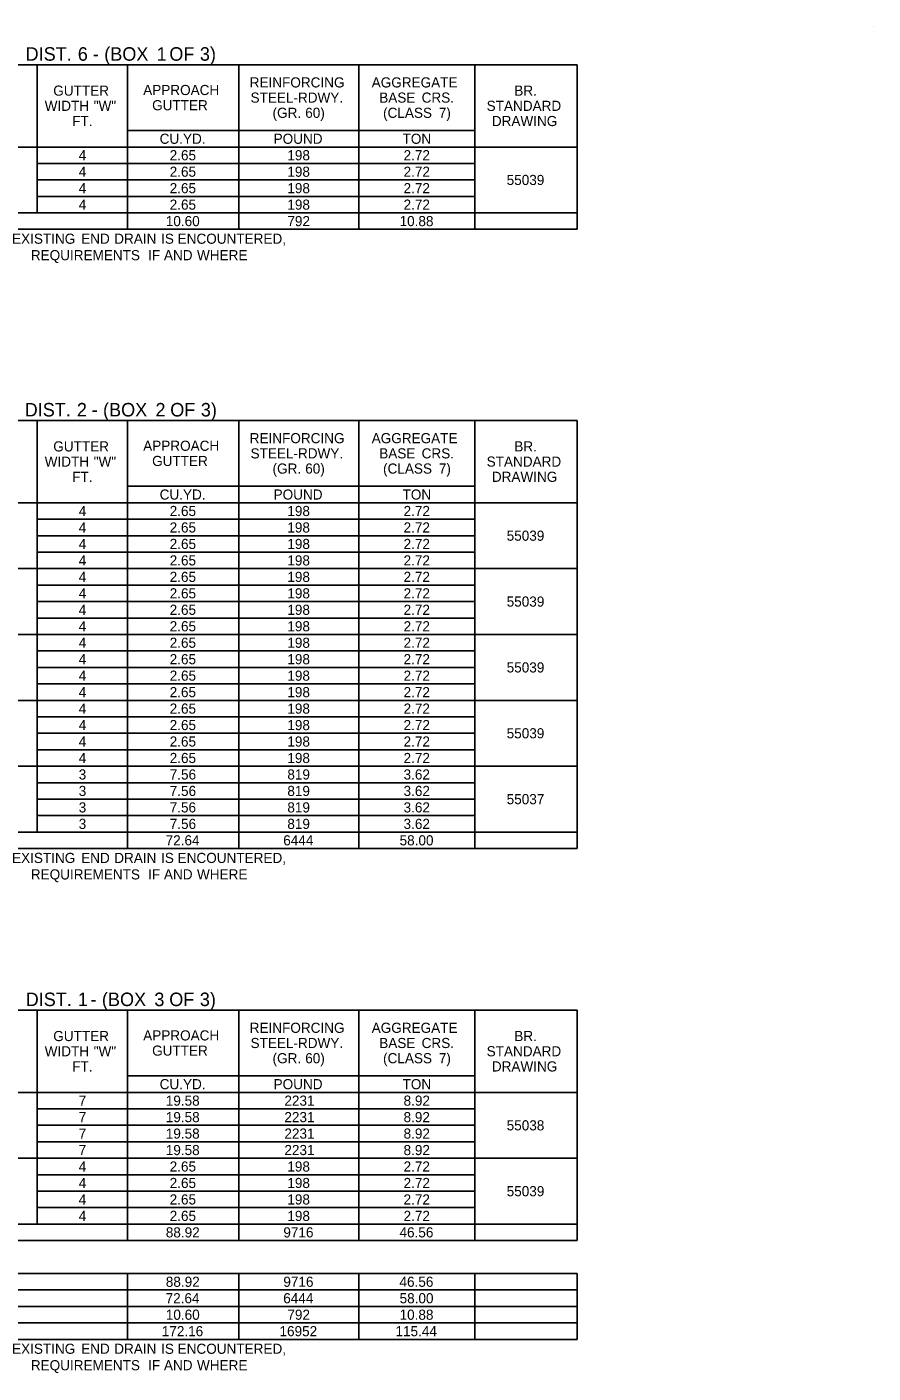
# Model space of a CAD drawing. Extents: x 542596 to 1930787, y -1948294 to 596640.
# Drawn here: x 559810 to 560311, y -1946903 to -1946106 of the extents above; entities that cross this region are included whole.
import ezdxf

# ---------------------------------------------------------------- set-up
doc = ezdxf.new("R2010")
doc.units = 0
doc.layers.add('Default', color=7, linetype='Continuous')

msp = doc.modelspace()

# ---------------------------------------------------------------- linework, layer by layer
at = {"layer": 'Default'}
for p, q in [((560311.42, -1946105.77), (560311.42, -1946105.77)), ((559473.59, -1946128.12), (560136.11, -1946128.12)), ((559816.31, -1946215.87), (559816.31, -1946128.12)), ((559869.93, -1946225.62), (559869.93, -1946128.12)), ((559935.74, -1946225.62), (559935.74, -1946128.12)), ((560006.92, -1946225.62), (560006.92, -1946128.12)), ((560075.66, -1946176.87), (560075.66, -1946128.12)), ((560075.66, -1946225.62), (560075.66, -1946128.12)), ((560136.11, -1946225.62), (560136.11, -1946128.12)), ((559869.93, -1946167.12), (560075.66, -1946167.12)), ((559935.74, -1946176.87), (559935.74, -1946167.12)), ((560006.92, -1946176.87), (560006.92, -1946167.12)), ((559473.59, -1946176.87), (560136.11, -1946176.87)), ((560075.66, -1946176.87), (560136.11, -1946176.87)), ((559816.31, -1946186.62), (560075.66, -1946186.62)), ((559869.93, -1946186.62), (560006.92, -1946186.62)), ((560006.92, -1946186.62), (560075.66, -1946186.62)), ((559816.31, -1946196.37), (560075.66, -1946196.37)), ((559869.93, -1946196.37), (560006.92, -1946196.37)), ((560006.92, -1946196.37), (560075.66, -1946196.37)), ((559816.31, -1946206.12), (560075.66, -1946206.12)), ((559869.93, -1946206.12), (560006.92, -1946206.12)), ((560006.92, -1946206.12), (560075.66, -1946206.12)), ((559473.59, -1946215.87), (560136.11, -1946215.87)), ((559762.68, -1946215.87), (559869.93, -1946215.87)), ((559869.93, -1946215.87), (560006.92, -1946215.87)), ((560006.92, -1946215.87), (560136.11, -1946215.87)), ((560006.92, -1946225.62), (560006.92, -1946215.87)), ((560075.66, -1946225.62), (560075.66, -1946215.87)), ((559473.59, -1946225.62), (560136.11, -1946225.62)), ((559473.59, -1946338.77), (560136.11, -1946338.77)), ((559816.31, -1946582.52), (559816.31, -1946338.77)), ((559869.93, -1946592.27), (559869.93, -1946338.77)), ((559935.74, -1946592.27), (559935.74, -1946338.77)), ((560006.92, -1946592.27), (560006.92, -1946338.77)), ((560075.66, -1946387.52), (560075.66, -1946338.77)), ((560075.66, -1946592.27), (560075.66, -1946338.77)), ((560136.11, -1946592.27), (560136.11, -1946338.77)), ((559869.93, -1946377.77), (560075.66, -1946377.77)), ((559935.74, -1946387.52), (559935.74, -1946377.77)), ((560006.92, -1946387.52), (560006.92, -1946377.77)), ((559473.59, -1946387.52), (560075.66, -1946387.52)), ((560075.66, -1946387.52), (560136.11, -1946387.52)), ((560075.66, -1946387.52), (560136.11, -1946387.52)), ((559816.31, -1946397.27), (560075.66, -1946397.27)), ((559869.93, -1946397.27), (560006.92, -1946397.27)), ((560006.92, -1946397.27), (560075.66, -1946397.27)), ((559816.31, -1946407.02), (560075.66, -1946407.02)), ((559869.93, -1946407.02), (560006.92, -1946407.02)), ((560006.92, -1946407.02), (560075.66, -1946407.02)), ((559816.31, -1946416.77), (560075.66, -1946416.77)), ((559869.93, -1946416.77), (560006.92, -1946416.77)), ((560006.92, -1946416.77), (560075.66, -1946416.77)), ((559473.59, -1946426.52), (560136.11, -1946426.52)), ((559762.68, -1946426.52), (559869.93, -1946426.52)), ((559869.93, -1946426.52), (560006.92, -1946426.52)), ((560006.92, -1946426.52), (560136.11, -1946426.52)), ((559816.31, -1946436.27), (560075.66, -1946436.27)), ((559869.93, -1946436.27), (560006.92, -1946436.27)), ((560006.92, -1946436.27), (560075.66, -1946436.27)), ((559816.31, -1946446.02), (560075.66, -1946446.02)), ((559869.93, -1946446.02), (560006.92, -1946446.02)), ((560006.92, -1946446.02), (560075.66, -1946446.02)), ((559816.31, -1946455.77), (560075.66, -1946455.77)), ((559869.93, -1946455.77), (560006.92, -1946455.77)), ((560006.92, -1946455.77), (560075.66, -1946455.77)), ((559473.59, -1946465.52), (560136.11, -1946465.52)), ((559762.68, -1946465.52), (559869.93, -1946465.52)), ((559869.93, -1946465.52), (560006.92, -1946465.52)), ((560006.92, -1946465.52), (560136.11, -1946465.52)), ((559816.31, -1946475.27), (560075.66, -1946475.27)), ((559869.93, -1946475.27), (560006.92, -1946475.27)), ((560006.92, -1946475.27), (560075.66, -1946475.27)), ((559816.31, -1946485.02), (560075.66, -1946485.02)), ((559869.93, -1946485.02), (560006.92, -1946485.02)), ((560006.92, -1946485.02), (560075.66, -1946485.02)), ((559816.31, -1946494.77), (560075.66, -1946494.77)), ((559869.93, -1946494.77), (560006.92, -1946494.77)), ((560006.92, -1946494.77), (560075.66, -1946494.77)), ((559473.59, -1946504.52), (560136.11, -1946504.52)), ((559762.68, -1946504.52), (559869.93, -1946504.52)), ((559869.93, -1946504.52), (560006.92, -1946504.52)), ((560006.92, -1946504.52), (560136.11, -1946504.52)), ((559816.31, -1946514.27), (560006.92, -1946514.27)), ((559816.31, -1946514.27), (559935.74, -1946514.27)), ((559935.74, -1946514.27), (560075.66, -1946514.27)), ((559816.31, -1946524.02), (560006.92, -1946524.02)), ((559816.31, -1946524.02), (559935.74, -1946524.02)), ((559935.74, -1946524.02), (560075.66, -1946524.02)), ((559816.31, -1946533.77), (560006.92, -1946533.77)), ((559816.31, -1946533.77), (559935.74, -1946533.77)), ((559935.74, -1946533.77), (560075.66, -1946533.77)), ((559473.59, -1946543.52), (560136.11, -1946543.52)), ((559762.68, -1946543.52), (559869.93, -1946543.52)), ((559869.93, -1946543.52), (560006.92, -1946543.52)), ((560006.92, -1946543.52), (560136.11, -1946543.52)), ((559816.31, -1946553.27), (560075.66, -1946553.27)), ((559869.93, -1946553.27), (560006.92, -1946553.27)), ((560006.92, -1946553.27), (560075.66, -1946553.27)), ((559816.31, -1946563.02), (560075.66, -1946563.02)), ((559869.93, -1946563.02), (560006.92, -1946563.02)), ((560006.92, -1946563.02), (560075.66, -1946563.02)), ((559816.31, -1946572.77), (560075.66, -1946572.77)), ((559869.93, -1946572.77), (560006.92, -1946572.77)), ((560006.92, -1946572.77), (560075.66, -1946572.77)), ((559473.59, -1946582.52), (560136.11, -1946582.52)), ((559762.68, -1946582.52), (559869.93, -1946582.52)), ((559869.93, -1946582.52), (560006.92, -1946582.52)), ((560006.92, -1946582.52), (560136.11, -1946582.52)), ((560006.92, -1946592.27), (560006.92, -1946582.52)), ((560075.66, -1946592.27), (560075.66, -1946582.52)), ((559473.59, -1946592.27), (560136.11, -1946592.27)), ((559473.59, -1946687.91), (560136.11, -1946687.91)), ((559816.31, -1946814.66), (559816.31, -1946687.91)), ((559869.93, -1946824.41), (559869.93, -1946687.91)), ((559935.74, -1946824.41), (559935.74, -1946687.91)), ((560006.92, -1946824.41), (560006.92, -1946687.91)), ((560075.66, -1946736.66), (560075.66, -1946687.91)), ((560075.66, -1946824.41), (560075.66, -1946687.91)), ((560136.11, -1946824.41), (560136.11, -1946687.91)), ((559869.93, -1946726.91), (560075.66, -1946726.91)), ((559935.74, -1946736.66), (559935.74, -1946726.91)), ((560006.92, -1946736.66), (560006.92, -1946726.91)), ((559473.59, -1946736.66), (560136.11, -1946736.66)), ((560075.66, -1946736.66), (560136.11, -1946736.66)), ((559816.31, -1946746.41), (560075.66, -1946746.41)), ((559869.93, -1946746.41), (560006.92, -1946746.41)), ((560006.92, -1946746.41), (560075.66, -1946746.41)), ((559816.31, -1946756.16), (560006.92, -1946756.16)), ((559816.31, -1946756.16), (559935.74, -1946756.16)), ((559935.74, -1946756.16), (560075.66, -1946756.16)), ((559816.31, -1946765.91), (560075.66, -1946765.91)), ((559869.93, -1946765.91), (560006.92, -1946765.91)), ((560006.92, -1946765.91), (560075.66, -1946765.91)), ((559473.59, -1946775.66), (560136.11, -1946775.66)), ((559762.68, -1946775.66), (559869.93, -1946775.66)), ((559869.93, -1946775.66), (560006.92, -1946775.66)), ((560006.92, -1946775.66), (560136.11, -1946775.66)), ((559816.31, -1946785.41), (560075.66, -1946785.41)), ((559869.93, -1946785.41), (560006.92, -1946785.41)), ((560006.92, -1946785.41), (560075.66, -1946785.41)), ((559816.31, -1946795.16), (560075.66, -1946795.16)), ((559869.93, -1946795.16), (560006.92, -1946795.16)), ((560006.92, -1946795.16), (560075.66, -1946795.16)), ((559816.31, -1946804.91), (560075.66, -1946804.91)), ((559869.93, -1946804.91), (560006.92, -1946804.91)), ((560006.92, -1946804.91), (560075.66, -1946804.91)), ((559473.59, -1946814.66), (560136.11, -1946814.66)), ((559762.68, -1946814.66), (559869.93, -1946814.66)), ((559869.93, -1946814.66), (560006.92, -1946814.66)), ((560006.92, -1946814.66), (560136.11, -1946814.66)), ((560006.92, -1946824.41), (560006.92, -1946814.66)), ((560075.66, -1946824.41), (560075.66, -1946814.66)), ((559473.59, -1946824.41), (560136.11, -1946824.41)), ((559473.59, -1946843.91), (560136.11, -1946843.91)), ((559473.59, -1946843.91), (560136.11, -1946843.91)), ((559869.93, -1946882.91), (559869.93, -1946843.91)), ((559935.74, -1946882.91), (559935.74, -1946843.91)), ((560006.92, -1946882.91), (560006.92, -1946843.91)), ((560075.66, -1946882.91), (560075.66, -1946843.91)), ((560136.11, -1946882.91), (560136.11, -1946843.91)), ((559473.59, -1946853.66), (560136.11, -1946853.66)), ((559473.59, -1946863.41), (560136.11, -1946863.41)), ((559473.59, -1946873.16), (560136.11, -1946873.16)), ((559869.93, -1946882.91), (559869.93, -1946873.16)), ((559935.74, -1946882.91), (559935.74, -1946873.16)), ((560006.92, -1946882.91), (560006.92, -1946873.16)), ((560075.66, -1946882.91), (560075.66, -1946873.16)), ((559473.59, -1946882.91), (560136.11, -1946882.91))]:
    msp.add_line(p, q, dxfattribs=at)

# ---------------------------------------------------------------- texts
for s, height, p in [(' DIST.', 8, (559806.55, -1946125.78)), (' 6', 8, (559837.46, -1946125.78)), (' (BOX', 8, (559853.12, -1946125.78)), (' 1', 8, (559884.16, -1946125.78)), (' OF', 8, (559891.66, -1946125.78)), (' 3)', 8, (559909.77, -1946125.78)), (' -', 8, (559846.38, -1946125.78)), ('GUTTER', 6, (559825.91, -1946146.49)), ('APPROACH', 6, (559879.17, -1946146.12)), ('REINFORCING', 6, (559942.24, -1946141.62)), ('AGGREGATE', 6, (560014.48, -1946141.62)), ('BR.', 6, (560098.95, -1946146.49)), ('WIDTH', 6, (559820.82, -1946155.49)), (' "W"', 6, (559847.65, -1946155.49)), ('GUTTER', 6, (559884.46, -1946155.12)), ('STEEL-RDWY.', 6, (559942.74, -1946150.62)), ('BASE', 6, (560018.96, -1946150.62)), (' CRS.', 6, (560041.84, -1946150.62)), ('STANDARD', 6, (560082.57, -1946155.49)), ('FT.', 6, (559837.12, -1946164.49)), ('(GR.', 6, (559955.77, -1946159.62)), (' 60)', 6, (559972.89, -1946159.62)), ('(CLASS', 6, (560021.22, -1946159.62)), (' 7)', 6, (560052.01, -1946159.62)), ('DRAWING', 6, (560085.64, -1946164.49)), ('CU.YD.', 6, (559888.92, -1946174.99)), ('POUND', 6, (559956.4, -1946174.99)), ('TON', 6, (560032.77, -1946174.99)), ('4', 6, (559840.99, -1946184.74)), ('2.65', 6, (559894.85, -1946184.74)), ('198', 6, (559964.53, -1946184.74)), ('2.72', 6, (560033.36, -1946184.74)), ('4', 6, (559840.99, -1946194.49)), ('2.65', 6, (559894.85, -1946194.49)), ('198', 6, (559964.53, -1946194.49)), ('2.72', 6, (560033.36, -1946194.49)), ('4', 6, (559840.99, -1946204.24)), ('2.65', 6, (559894.85, -1946204.24)), ('198', 6, (559964.53, -1946204.24)), ('2.72', 6, (560033.36, -1946204.24)), ('55039', 6, (560094.42, -1946199.37)), ('4', 6, (559840.99, -1946213.99)), ('2.65', 6, (559894.85, -1946213.99)), ('198', 6, (559964.53, -1946213.99)), ('2.72', 6, (560033.36, -1946213.99)), ('10.60', 6, (559892.56, -1946223.74)), ('792', 6, (559964.55, -1946223.74)), ('10.88', 6, (560030.99, -1946223.74)), (' EXISTING', 6, (559799.27, -1946234.17)), (' END', 6, (559840.21, -1946234.17)), (' DRAIN', 6, (559859.79, -1946234.17)), (' IS', 6, (559887.52, -1946234.17)), (' ENCOUNTERED,', 6, (559897.33, -1946234.17)), (' REQUIREMENTS', 6, (559810.39, -1946243.92)), (' IF', 6, (559879.83, -1946243.92)), (' AND', 6, (559889.22, -1946243.92)), (' WHERE', 6, (559908.8, -1946243.92)), (' DIST.', 8, (559806.01, -1946336.43)), (' 2', 8, (559836.91, -1946336.43)), (' -', 8, (559845.67, -1946336.43)), (' (BOX', 8, (559852.41, -1946336.43)), (' 2', 8, (559883.45, -1946336.43)), (' OF', 8, (559892.21, -1946336.43)), (' 3)', 8, (559910.32, -1946336.43)), ('REINFORCING', 6, (559942.24, -1946352.27)), ('AGGREGATE', 6, (560014.48, -1946352.27)), ('GUTTER', 6, (559825.91, -1946357.15)), ('APPROACH', 6, (559879.17, -1946356.77)), ('STEEL-RDWY.', 6, (559942.74, -1946361.27)), ('BASE', 6, (560018.96, -1946361.27)), (' CRS.', 6, (560041.84, -1946361.27)), ('BR.', 6, (560098.95, -1946357.15)), ('WIDTH', 6, (559820.82, -1946366.15)), (' "W"', 6, (559847.65, -1946366.15)), ('GUTTER', 6, (559884.46, -1946365.77)), ('(GR.', 6, (559955.77, -1946370.27)), (' 60)', 6, (559972.89, -1946370.27)), ('(CLASS', 6, (560021.22, -1946370.27)), (' 7)', 6, (560052.01, -1946370.27)), ('STANDARD', 6, (560082.57, -1946366.15)), ('FT.', 6, (559837.12, -1946375.15)), ('DRAWING', 6, (560085.64, -1946375.15)), ('CU.YD.', 6, (559888.92, -1946385.65)), ('POUND', 6, (559956.4, -1946385.65)), ('TON', 6, (560032.77, -1946385.65)), ('4', 6, (559840.99, -1946395.4)), ('2.65', 6, (559894.85, -1946395.4)), ('198', 6, (559964.53, -1946395.4)), ('2.72', 6, (560033.36, -1946395.4)), ('4', 6, (559840.99, -1946405.15)), ('2.65', 6, (559894.85, -1946405.15)), ('198', 6, (559964.53, -1946405.15)), ('2.72', 6, (560033.36, -1946405.15)), ('55039', 6, (560094.42, -1946410.02)), ('4', 6, (559840.99, -1946414.9)), ('2.65', 6, (559894.85, -1946414.9)), ('198', 6, (559964.53, -1946414.9)), ('2.72', 6, (560033.36, -1946414.9)), ('4', 6, (559840.99, -1946424.65)), ('2.65', 6, (559894.85, -1946424.65)), ('198', 6, (559964.53, -1946424.65)), ('2.72', 6, (560033.36, -1946424.65)), ('4', 6, (559840.99, -1946434.4)), ('2.65', 6, (559894.85, -1946434.4)), ('198', 6, (559964.53, -1946434.4)), ('2.72', 6, (560033.36, -1946434.4)), ('4', 6, (559840.99, -1946444.15)), ('2.65', 6, (559894.85, -1946444.15)), ('198', 6, (559964.53, -1946444.15)), ('2.72', 6, (560033.36, -1946444.15)), ('55039', 6, (560094.42, -1946449.02)), ('4', 6, (559840.99, -1946453.9)), ('2.65', 6, (559894.85, -1946453.9)), ('198', 6, (559964.53, -1946453.9)), ('2.72', 6, (560033.36, -1946453.9)), ('4', 6, (559840.99, -1946463.65)), ('2.65', 6, (559894.85, -1946463.65)), ('198', 6, (559964.53, -1946463.65)), ('2.72', 6, (560033.36, -1946463.65)), ('4', 6, (559840.99, -1946473.4)), ('2.65', 6, (559894.85, -1946473.4)), ('198', 6, (559964.53, -1946473.4)), ('2.72', 6, (560033.36, -1946473.4)), ('4', 6, (559840.99, -1946483.15)), ('2.65', 6, (559894.85, -1946483.15)), ('198', 6, (559964.53, -1946483.15)), ('2.72', 6, (560033.36, -1946483.15)), ('55039', 6, (560094.42, -1946488.02)), ('4', 6, (559840.99, -1946492.9)), ('2.65', 6, (559894.85, -1946492.9)), ('198', 6, (559964.53, -1946492.9)), ('2.72', 6, (560033.36, -1946492.9)), ('4', 6, (559840.99, -1946502.65)), ('2.65', 6, (559894.85, -1946502.65)), ('198', 6, (559964.53, -1946502.65)), ('2.72', 6, (560033.36, -1946502.65)), ('4', 6, (559840.99, -1946512.4)), ('2.65', 6, (559894.85, -1946512.4)), ('198', 6, (559964.53, -1946512.4)), ('2.72', 6, (560033.36, -1946512.4)), ('4', 6, (559840.99, -1946522.15)), ('2.65', 6, (559894.85, -1946522.15)), ('198', 6, (559964.53, -1946522.15)), ('2.72', 6, (560033.36, -1946522.15)), ('4', 6, (559840.99, -1946531.9)), ('2.65', 6, (559894.85, -1946531.9)), ('198', 6, (559964.53, -1946531.9)), ('2.72', 6, (560033.36, -1946531.9)), ('55039', 6, (560094.42, -1946527.02)), ('4', 6, (559840.99, -1946541.65)), ('2.65', 6, (559894.85, -1946541.65)), ('198', 6, (559964.53, -1946541.65)), ('2.72', 6, (560033.36, -1946541.65)), ('3', 6, (559840.98, -1946551.4)), ('7.56', 6, (559894.87, -1946551.4)), ('819', 6, (559964.53, -1946551.4)), ('3.62', 6, (560033.36, -1946551.4)), ('3', 6, (559840.98, -1946561.15)), ('7.56', 6, (559894.87, -1946561.15)), ('819', 6, (559964.53, -1946561.15)), ('3.62', 6, (560033.36, -1946561.15)), ('3', 6, (559840.98, -1946570.9)), ('7.56', 6, (559894.87, -1946570.9)), ('819', 6, (559964.53, -1946570.9)), ('3.62', 6, (560033.36, -1946570.9)), ('55037', 6, (560094.42, -1946566.02)), ('3', 6, (559840.98, -1946580.65)), ('7.56', 6, (559894.87, -1946580.65)), ('819', 6, (559964.53, -1946580.65)), ('3.62', 6, (560033.36, -1946580.65)), ('72.64', 6, (559892.45, -1946590.4)), ('6444', 6, (559962.11, -1946590.4)), ('58.00', 6, (560031.01, -1946590.4)), (' EXISTING', 6, (559799.27, -1946600.82)), (' END', 6, (559840.21, -1946600.82)), (' DRAIN', 6, (559859.79, -1946600.82)), (' IS', 6, (559887.52, -1946600.82)), (' ENCOUNTERED,', 6, (559897.33, -1946600.82)), (' REQUIREMENTS', 6, (559810.39, -1946610.57)), (' IF', 6, (559879.83, -1946610.57)), (' AND', 6, (559889.22, -1946610.57)), (' WHERE', 6, (559908.8, -1946610.57)), (' (BOX', 8, (559851.75, -1946685.57)), (' 3)', 8, (559909.73, -1946685.57)), (' DIST.', 8, (559806.6, -1946685.57)), (' 1', 8, (559837.5, -1946685.57)), (' -', 8, (559845.01, -1946685.57)), (' 3', 8, (559882.79, -1946685.57)), (' OF', 8, (559891.62, -1946685.57)), ('GUTTER', 6, (559825.91, -1946706.29)), ('APPROACH', 6, (559879.17, -1946705.91)), ('REINFORCING', 6, (559942.24, -1946701.41)), ('AGGREGATE', 6, (560014.48, -1946701.41)), ('BR.', 6, (560098.95, -1946706.29)), ('GUTTER', 6, (559884.46, -1946714.91)), ('STEEL-RDWY.', 6, (559942.74, -1946710.41)), ('BASE', 6, (560018.96, -1946710.41)), (' CRS.', 6, (560041.84, -1946710.41)), ('STANDARD', 6, (560082.57, -1946715.29)), ('WIDTH', 6, (559820.82, -1946715.29)), (' "W"', 6, (559847.65, -1946715.29)), ('(GR.', 6, (559955.77, -1946719.41)), (' 60)', 6, (559972.89, -1946719.41)), ('(CLASS', 6, (560021.22, -1946719.41)), (' 7)', 6, (560052.01, -1946719.41)), ('FT.', 6, (559837.12, -1946724.29)), ('DRAWING', 6, (560085.64, -1946724.29)), ('CU.YD.', 6, (559888.92, -1946734.79)), ('POUND', 6, (559956.4, -1946734.79)), ('TON', 6, (560032.77, -1946734.79)), ('7', 6, (559840.98, -1946744.54)), ('19.58', 6, (559892.54, -1946744.54)), ('2231', 6, (559962.78, -1946744.54)), ('8.92', 6, (560033.36, -1946744.54)), ('7', 6, (559840.98, -1946754.29)), ('19.58', 6, (559892.54, -1946754.29)), ('2231', 6, (559962.78, -1946754.29)), ('8.92', 6, (560033.36, -1946754.29)), ('55038', 6, (560094.42, -1946759.16)), ('7', 6, (559840.98, -1946764.04)), ('19.58', 6, (559892.54, -1946764.04)), ('2231', 6, (559962.78, -1946764.04)), ('8.92', 6, (560033.36, -1946764.04)), ('7', 6, (559840.98, -1946773.79)), ('19.58', 6, (559892.54, -1946773.79)), ('2231', 6, (559962.78, -1946773.79)), ('8.92', 6, (560033.36, -1946773.79)), ('4', 6, (559840.99, -1946783.54)), ('2.65', 6, (559894.85, -1946783.54)), ('198', 6, (559964.53, -1946783.54)), ('2.72', 6, (560033.36, -1946783.54)), ('4', 6, (559840.99, -1946793.29)), ('2.65', 6, (559894.85, -1946793.29)), ('198', 6, (559964.53, -1946793.29)), ('2.72', 6, (560033.36, -1946793.29)), ('55039', 6, (560094.42, -1946798.16)), ('4', 6, (559840.99, -1946803.04)), ('2.65', 6, (559894.85, -1946803.04)), ('198', 6, (559964.53, -1946803.04)), ('2.72', 6, (560033.36, -1946803.04)), ('4', 6, (559840.99, -1946812.79)), ('2.65', 6, (559894.85, -1946812.79)), ('198', 6, (559964.53, -1946812.79)), ('2.72', 6, (560033.36, -1946812.79)), ('88.92', 6, (559892.56, -1946822.54)), ('9716', 6, (559962.16, -1946822.54)), ('46.56', 6, (560030.95, -1946822.54)), ('88.92', 6, (559892.56, -1946851.79)), ('9716', 6, (559962.16, -1946851.79)), ('46.56', 6, (560030.95, -1946851.79)), ('72.64', 6, (559892.45, -1946861.54)), ('6444', 6, (559962.11, -1946861.54)), ('58.00', 6, (560031.01, -1946861.54)), ('10.60', 6, (559892.56, -1946871.29)), ('792', 6, (559964.55, -1946871.29)), ('10.88', 6, (560030.99, -1946871.29)), ('172.16', 6, (559890.17, -1946881.04)), ('16952', 6, (559959.89, -1946881.04)), ('115.44', 6, (560028.57, -1946881.04)), (' EXISTING', 6, (559799.27, -1946891.46)), (' END', 6, (559840.21, -1946891.46)), (' DRAIN', 6, (559859.79, -1946891.46)), (' IS', 6, (559887.52, -1946891.46)), (' ENCOUNTERED,', 6, (559897.33, -1946891.46)), (' REQUIREMENTS', 6, (559810.39, -1946901.21)), (' IF', 6, (559879.83, -1946901.21)), (' AND', 6, (559889.22, -1946901.21)), (' WHERE', 6, (559908.8, -1946901.21))]:
    msp.add_text(s, height=height, dxfattribs=at).set_placement(p)

doc.saveas('drawing.dxf')
